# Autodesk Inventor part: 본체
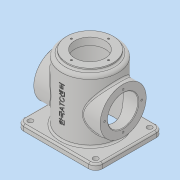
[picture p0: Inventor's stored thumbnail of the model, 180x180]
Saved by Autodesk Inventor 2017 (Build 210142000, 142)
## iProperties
Part Number: 본체
Material: 일반
Document SubType Name: Modeling
Designer: MRC
Mass: 457.509 g
Surface Area: 1067.89 cm^2
Volume: 457.509 cm^3
Density: 1 g/cm^3
Appearance: 기본값
Author: MRC
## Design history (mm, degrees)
sketch "스케치1"
  geometry: C1 r 50 at (0, 0); 1 further point
  constraints: 1 centre point, 1 coincident
  dimensions: "d0" = 100 diameter of C1
extrude "돌출1" new body sketch "스케치1" stored distance "d1" = 120; taper "d2" = 0 deg
sketch "스케치3"
  geometry: C1 r 41 at (0, 0); 1 further point
  constraints: 1 centre point, 1 coincident
  dimensions: "d7" = 82 diameter of C1
extrude "돌출3" join sketch "스케치3" stored distance "d8" = 118; taper "d9" = 0 deg
sketch "스케치4"
  geometry: C1 r 27 at (0, 0); 1 further point
  constraints: 1 centre point, 1 coincident
  dimensions: "d10" = 54 diameter of C1
extrude "돌출4" cut sketch "스케치4" stored distance "d11" = 118; taper "d12" = 0 deg
sketch "스케치5"
  geometry: L1 (-70, -60)-(70, -60); L2 (70, -60)-(70, 60); L3 (70, 60)-(-70, 60); L4 (-70, 60)-(-70, -60); L5 (-70, -60)-(70, 60); L6 (70, -60)-(-70, 60); C1 r 50 at (0, 0) reference
  constraints: 12 end point, 2 midpoint, 2 parallel, 1 horizontal, 1 perpendicular
  dimensions: "d13" = 140 distance of L3.end L2.end; "d14" = 120 distance of L2.end L1.end
extrude "돌출5" join sketch "스케치5" distance "d15" = 10; taper "d16" = 0 deg
fillet "모깎기1" dims "d26" = 6
fillet "모깎기4" dims "d29" = 3
fillet "모깎기6" dims "d31" = 12
chamfer "모따기2" distance "d36" = 1; stored, may be unused: second distance "d37" = 2, angle "d38" = 45 deg
sketch "스케치10"
  geometry: C1 r 41 at (0, 0) reference; 4 further points
  constraints: 1 vertical alignment, 5 other
  dimensions: "d46" = 33 distance of C1.centre point (0, 33); "d49" = 360 deg dimension on C1.centre point (0, 33) (derived)
hole "구멍2" sketch "스케치10" at (0, 33), (-33, 0), (0, -33), (33, 0) diameter "d51" = 3.242; stored, may be unused: countersink angle "d55" = 90 deg, drill point angle "d57" = 118 deg; dims "d52" = 8, "d53" = 4, "d54" = 2, "d56" = 10
node "작업 평면1"
sketch "스케치12"
  geometry: L1 (58, -60)-(-58, -60) reference; 6 further points; 1 other entity
  constraints: 1 vertical alignment, 2 other
  dimensions: "d90" = 66 distance from line of L1 point (0, 6)
feature "엠보싱1" sketch "스케치12" dims "d72" = 0.5, "d73" = 0
sketch "스케치16"
  geometry: C1 r 42 at (0, 0); 1 further point
  constraints: 1 centre point, 1 coincident
  dimensions: "d77" = 84 diameter of C1
extrude "돌출10" cut sketch "스케치16" distance "d78" = 112; taper "d79" = 0 deg
sketch "스케치17"
  geometry: C1 r 44 at (0, 0) reference; C2 r 41 at (0, 0)
  constraints: 1 centre point, 1 coincident
  dimensions: "d80" = 82 diameter of C2
extrude "돌출11" join sketch "스케치17" distance "d81" = 5; taper "d82" = 0 deg
sketch "스케치18"
  geometry: C1 r 42 at (0, 0) reference; C2 r 27 at (0, 0)
  constraints: 1 centre point, 1 coincident
  dimensions: "d83" = 54 diameter of C2
extrude "돌출12" cut sketch "스케치18" stored distance "d84" = 5; taper "d85" = 0 deg
fillet "모깎기8" dims "d86" = 3
sketch "스케치19"
  geometry: C1 r 4.5 at (58, 48); A1 r 9 centre (58, 48) between (67, 48) and (58, 57) reference
  constraints: 1 centre point, 1 coincident
  dimensions: "d87" = 9 diameter of C1
extrude "돌출13" cut sketch "스케치19" stored distance "d88" = 5; taper "d89" = 0 deg
sketch "스케치20"
  geometry: C1 r 27 at (0, 0) reference; C2 r 41 at (0, 0) reference; 4 further points
  constraints: 1 vertical alignment, 5 other
  dimensions: "d91" = 33 distance of C1.centre point (0, 33); "d94" = 360 deg dimension on C2.centre point (0, 33) (derived)
hole "구멍4" sketch "스케치20" at (0, 33), (-33, 0), (0, -33), (33, 0) diameter "d96" = 3.242; stored, may be unused: countersink angle "d100" = 90 deg, drill point angle "d102" = 118 deg; dims "d97" = 8, "d98" = 4, "d99" = 2, "d101" = 10
node "솔리드1"
mirror "미러1"
mirror "미러2"
mirror "미러3"
